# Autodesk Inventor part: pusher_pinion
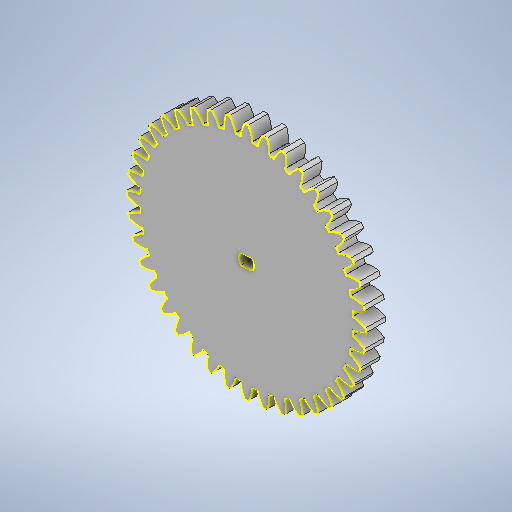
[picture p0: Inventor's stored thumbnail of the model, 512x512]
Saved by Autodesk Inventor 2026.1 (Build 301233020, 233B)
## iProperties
Company: meta-matic.com
Created: 2026-10
Part Number: pusher_pinion
Material: Generic
Description: Spur Gear - meta-matic-generator 1.3
Document SubType Name: Modeling
Designer: alolo
Authority: META-MATIC-ID: 1c046b0d7dfa
Density: 1 g/cm^3
Appearance: Default
Sending System: Open CASCADE
Preprocessor: meta-matic-generator 1.3
Title: Spur Gear_1c046b0d7dfa
Author: Takahashi Mizuki @tkhsmz
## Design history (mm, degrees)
feature "Base1"
sketch "Sketch1"
  geometry: L1 (-41.744, 1.365)-(-37.899, 1.365); L2 (-41.744, -2.135)-(-37.899, -2.135); A1 r 2.6 centre (-39.822, -0.385) between (-41.744, 1.365) and (-37.899, 1.365); 3 further points
  constraints: 4 end point, 4 point on circle, 2 midpoint, 1 centre point, 1 coincident, 1 horizontal, 1 parallel
  dimensions: "d0" = 5.2 diameter of A1; "d6" = 1.75 distance of point (-39.822, -0.385) point (-39.822, 1.365); "d7" = 1.75 distance of point (-39.822, -2.135) point (-39.822, -0.385) (= d6)
extrude "Extrusion1" cut sketch "Sketch1" stored distance "d1" = 10; taper "d2" = 0 deg
sketch "Sketch2"
  geometry: L1 (-2.379, -2.46)-(-2.292, -2.465) reference; L2 (-2.235, -0.635)-(-2.322, -0.634) reference; L3 (-2.515, 3.423)-(-2.428, 3.431) reference; L4 (-2.658, 5.248)-(-2.745, 5.235) reference; L5 (-3.57, 9.212)-(-3.485, 9.234) reference; L6 (-3.997, 10.993)-(-4.081, 10.966) reference; L7 (-5.518, 14.764)-(-5.438, 14.8) reference; L8 (-6.218, 16.457)-(-6.296, 16.418) reference; L9 (-8.31, 19.944)-(-8.236, 19.992) reference; L10 (-9.266, 21.506)-(-9.338, 21.455) reference; L11 (-11.878, 24.624)-(-11.813, 24.682) reference; L12 (-13.067, 26.017)-(-13.129, 25.955) reference; L13 (-16.134, 28.687)-(-16.079, 28.755) reference; L14 (-17.526, 29.877)-(-17.578, 29.806) reference; L15 (-20.974, 32.035)-(-20.93, 32.11) reference; L16 (-22.535, 32.992)-(-22.575, 32.914) reference; L17 (-26.277, 34.584)-(-26.246, 34.666) reference; L18 (-27.969, 35.285)-(-27.997, 35.202) reference; L19 (-31.914, 36.272)-(-31.896, 36.358) reference; L20 (-33.695, 36.7)-(-33.709, 36.614) reference; L21 (-37.746, 37.058)-(-37.741, 37.145) reference; L22 (-39.572, 37.202)-(-39.572, 37.115) reference; L23 (-43.629, 36.922)-(-43.638, 37.009) reference; L24 (-45.455, 36.779)-(-45.442, 36.692) reference; L25 (-49.418, 35.867)-(-49.44, 35.951) reference; L26 (-51.199, 35.44)-(-51.172, 35.356) reference; L27 (-54.971, 33.919)-(-55.006, 33.999) reference; L28 (-56.663, 33.219)-(-56.624, 33.141) reference; L29 (-60.151, 31.127)-(-60.198, 31.201) reference; L30 (-61.712, 30.171)-(-61.661, 30.099) reference; L31 (-64.83, 27.559)-(-64.888, 27.624) reference; L32 (-66.223, 26.37)-(-66.161, 26.308) reference; L33 (-68.893, 23.303)-(-68.961, 23.358) reference; L34 (-70.083, 21.911)-(-70.013, 21.858) reference; L35 (-72.241, 18.463)-(-72.317, 18.507) reference; L36 (-73.198, 16.902)-(-73.12, 16.862) reference; L37 (-74.79, 13.16)-(-74.872, 13.191) reference; L38 (-75.492, 11.468)-(-75.408, 11.44) reference; L39 (-76.478, 7.523)-(-76.564, 7.541) reference; L40 (-76.907, 5.742)-(-76.82, 5.728) reference; L41 (-77.264, 1.691)-(-77.352, 1.696) reference; L42 (-77.408, -0.135)-(-77.321, -0.135) reference; L43 (-77.128, -4.192)-(-77.215, -4.201) reference; L44 (-76.985, -6.018)-(-76.898, -6.005) reference; L45 (-76.073, -9.981)-(-76.158, -10.003) reference; L46 (-75.646, -11.762)-(-75.562, -11.735) reference; L47 (-74.125, -15.534)-(-74.206, -15.569) reference; L48 (-73.425, -17.226)-(-73.347, -17.187) reference; L49 (-71.333, -20.714)-(-71.407, -20.761) reference; L50 (-70.377, -22.276)-(-70.306, -22.224) reference; L51 (-67.765, -25.393)-(-67.831, -25.451) reference; L52 (-66.576, -26.786)-(-66.514, -26.724) reference; L53 (-63.509, -29.456)-(-63.564, -29.524) reference; L54 (-62.117, -30.646)-(-62.065, -30.576) reference; L55 (-58.67, -32.804)-(-58.714, -32.88) reference; L56 (-57.108, -33.761)-(-57.068, -33.683) reference; L57 (-53.366, -35.353)-(-53.398, -35.435) reference; L58 (-51.674, -36.055)-(-51.647, -35.971) reference; L59 (-47.729, -37.041)-(-47.747, -37.127) reference; L60 (-45.948, -37.47)-(-45.934, -37.383) reference; L61 (-41.897, -37.827)-(-41.902, -37.915) reference; L62 (-40.071, -37.972)-(-40.071, -37.884) reference; L63 (-36.014, -37.691)-(-36.005, -37.778) reference; L64 (-34.189, -37.548)-(-34.202, -37.461) reference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; A1 r 2.6 centre (-39.822, -0.385) between (-37.899, -2.135) and (-37.899, 1.365) reference; A2 r 37.5 centre (-39.822, -0.385) between (-2.379, -2.46) and (-2.322, -0.634) reference; A3 r 42 centre (-39.822, -0.385) between (2.16, 0.851) and (2.088, 2.37) reference; A4 r 37.5 centre (-39.822, -0.385) between (-2.515, 3.423) and (-2.745, 5.235) reference; A5 r 42 centre (-39.822, -0.385) between (1.45, 7.403) and (1.141, 8.892) reference; A6 r 37.5 centre (-39.822, -0.385) between (-3.57, 9.212) and (-4.081, 10.966) reference; A7 r 42 centre (-39.822, -0.385) between (-0.276, 13.763) and (-0.815, 15.186) reference; A8 r 37.5 centre (-39.822, -0.385) between (-5.518, 14.764) and (-6.296, 16.418) reference; A9 r 42 centre (-39.822, -0.385) between (-2.976, 19.775) and (-3.731, 21.096) reference; A10 r 37.5 centre (-39.822, -0.385) between (-8.31, 19.944) and (-9.338, 21.455) reference; A11 r 42 centre (-39.822, -0.385) between (-6.584, 25.291) and (-7.535, 26.478) reference; A12 r 37.5 centre (-39.822, -0.385) between (-11.878, 24.624) and (-13.129, 25.955) reference; A13 r 42 centre (-39.822, -0.385) between (-11.009, 30.174) and (-12.135, 31.198) reference; A14 r 37.5 centre (-39.822, -0.385) between (-16.134, 28.687) and (-17.578, 29.806) reference; A15 r 42 centre (-39.822, -0.385) between (-16.145, 34.305) and (-17.416, 35.14) reference; A16 r 37.5 centre (-39.822, -0.385) between (-20.974, 32.035) and (-22.575, 32.914) reference; A17 r 42 centre (-39.822, -0.385) between (-21.863, 37.582) and (-23.25, 38.208) reference; A18 r 37.5 centre (-39.822, -0.385) between (-26.277, 34.584) and (-27.997, 35.202) reference; A19 r 42 centre (-39.822, -0.385) between (-28.023, 39.924) and (-29.491, 40.325) reference; A20 r 37.5 centre (-39.822, -0.385) between (-31.914, 36.272) and (-33.709, 36.614) reference; A21 r 42 centre (-39.822, -0.385) between (-34.474, 41.274) and (-35.986, 41.44) reference; A22 r 37.5 centre (-39.822, -0.385) between (-37.746, 37.058) and (-39.572, 37.115) reference; A23 r 42 centre (-39.822, -0.385) between (-41.057, 41.597) and (-42.576, 41.525) reference; A24 r 37.5 centre (-39.822, -0.385) between (-43.629, 36.922) and (-45.442, 36.692) reference; A25 r 42 centre (-39.822, -0.385) between (-47.609, 40.887) and (-49.099, 40.578) reference; A26 r 37.5 centre (-39.822, -0.385) between (-49.418, 35.867) and (-51.172, 35.356) reference; A27 r 42 centre (-39.822, -0.385) between (-53.97, 39.161) and (-55.392, 38.622) reference; A28 r 37.5 centre (-39.822, -0.385) between (-54.971, 33.919) and (-56.624, 33.141) reference; A29 r 42 centre (-39.822, -0.385) between (-59.982, 36.461) and (-61.303, 35.706) reference; A30 r 37.5 centre (-39.822, -0.385) between (-60.151, 31.127) and (-61.661, 30.099) reference; A31 r 42 centre (-39.822, -0.385) between (-65.497, 32.853) and (-66.684, 31.902) reference; A32 r 37.5 centre (-39.822, -0.385) between (-64.83, 27.559) and (-66.161, 26.308) reference; A33 r 42 centre (-39.822, -0.385) between (-70.381, 28.428) and (-71.404, 27.302) reference; A34 r 37.5 centre (-39.822, -0.385) between (-68.893, 23.303) and (-70.013, 21.858) reference; A35 r 42 centre (-39.822, -0.385) between (-74.512, 23.292) and (-75.346, 22.02) reference; A36 r 37.5 centre (-39.822, -0.385) between (-72.241, 18.463) and (-73.12, 16.862) reference; A37 r 42 centre (-39.822, -0.385) between (-77.788, 17.574) and (-78.414, 16.187) reference; A38 r 37.5 centre (-39.822, -0.385) between (-74.79, 13.16) and (-75.408, 11.44) reference; A39 r 42 centre (-39.822, -0.385) between (-80.13, 11.414) and (-80.531, 9.946) reference; A40 r 37.5 centre (-39.822, -0.385) between (-76.478, 7.523) and (-76.82, 5.728) reference; A41 r 42 centre (-39.822, -0.385) between (-81.48, 4.963) and (-81.646, 3.451) reference; A42 r 37.5 centre (-39.822, -0.385) between (-77.264, 1.691) and (-77.321, -0.135) reference; A43 r 42 centre (-39.822, -0.385) between (-81.803, -1.62) and (-81.731, -3.139) reference; A44 r 37.5 centre (-39.822, -0.385) between (-77.128, -4.192) and (-76.898, -6.005) reference; A45 r 42 centre (-39.822, -0.385) between (-81.093, -8.172) and (-80.784, -9.662) reference; A46 r 37.5 centre (-39.822, -0.385) between (-76.073, -9.981) and (-75.562, -11.735) reference; A47 r 42 centre (-39.822, -0.385) between (-79.367, -14.533) and (-78.829, -15.955) reference; A48 r 37.5 centre (-39.822, -0.385) between (-74.125, -15.534) and (-73.347, -17.187) reference; A49 r 42 centre (-39.822, -0.385) between (-76.667, -20.545) and (-75.913, -21.866) reference; A50 r 37.5 centre (-39.822, -0.385) between (-71.333, -20.714) and (-70.306, -22.224) reference; A51 r 42 centre (-39.822, -0.385) between (-73.06, -26.06) and (-72.108, -27.247) reference; A52 r 37.5 centre (-39.822, -0.385) between (-67.765, -25.393) and (-66.514, -26.724) reference; A53 r 42 centre (-39.822, -0.385) between (-68.634, -30.944) and (-67.508, -31.967) reference; A54 r 37.5 centre (-39.822, -0.385) between (-63.509, -29.456) and (-62.065, -30.576) reference; A55 r 42 centre (-39.822, -0.385) between (-63.499, -35.075) and (-62.227, -35.909) reference; A56 r 37.5 centre (-39.822, -0.385) between (-58.67, -32.804) and (-57.068, -33.683) reference; A57 r 42 centre (-39.822, -0.385) between (-57.78, -38.352) and (-56.394, -38.977) reference; A58 r 37.5 centre (-39.822, -0.385) between (-53.366, -35.353) and (-51.647, -35.971) reference; A59 r 42 centre (-39.822, -0.385) between (-51.62, -40.693) and (-50.152, -41.094) reference; A60 r 37.5 centre (-39.822, -0.385) between (-47.729, -37.041) and (-45.934, -37.383) reference; A61 r 42 centre (-39.822, -0.385) between (-45.169, -42.043) and (-43.657, -42.209) reference; A62 r 37.5 centre (-39.822, -0.385) between (-41.897, -37.827) and (-40.071, -37.884) reference; A63 r 42 centre (-39.822, -0.385) between (-38.586, -42.366) and (-37.067, -42.294) reference; A64 r 37.5 centre (-39.822, -0.385) between (-36.014, -37.691) and (-34.202, -37.461) reference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; 1 further point
  constraints: 80 other
extrude "Extrusion2" cut sketch "Sketch2" distance "d3" = 3; taper "d4" = 0 deg
sketch "Sketch3"
  geometry: L1 (-41.744, -2.135)-(-37.899, -2.135) reference; L2 (-37.899, 1.365)-(-41.744, 1.365) reference; L3 (-2.515, 3.423)-(-2.428, 3.431) reference; L4 (-2.658, 5.248)-(-2.745, 5.235) reference; L5 (-3.57, 9.212)-(-3.485, 9.234) reference; L6 (-3.997, 10.993)-(-4.081, 10.966) reference; L7 (-5.518, 14.764)-(-5.438, 14.8) reference; L8 (-6.218, 16.457)-(-6.296, 16.418) reference; L9 (-8.31, 19.944)-(-8.236, 19.992) reference; L10 (-9.266, 21.506)-(-9.338, 21.455) reference; L11 (-11.878, 24.624)-(-11.813, 24.682) reference; L12 (-13.067, 26.017)-(-13.129, 25.955) reference; L13 (-16.134, 28.687)-(-16.079, 28.755) reference; L14 (-17.526, 29.877)-(-17.578, 29.806) reference; L15 (-20.974, 32.035)-(-20.93, 32.11) reference; L16 (-22.535, 32.992)-(-22.575, 32.914) reference; L17 (-26.277, 34.584)-(-26.246, 34.666) reference; L18 (-27.969, 35.285)-(-27.997, 35.202) reference; L19 (-31.914, 36.272)-(-31.896, 36.358) reference; L20 (-33.695, 36.7)-(-33.709, 36.614) reference; L21 (-37.746, 37.058)-(-37.741, 37.145) reference; L22 (-39.572, 37.202)-(-39.572, 37.115) reference; L23 (-43.629, 36.922)-(-43.638, 37.009) reference; L24 (-45.455, 36.779)-(-45.442, 36.692) reference; L25 (-49.418, 35.867)-(-49.44, 35.951) reference; L26 (-51.199, 35.44)-(-51.172, 35.356) reference; L27 (-54.971, 33.919)-(-55.006, 33.999) reference; L28 (-56.663, 33.219)-(-56.624, 33.141) reference; L29 (-60.151, 31.127)-(-60.198, 31.201) reference; L30 (-61.712, 30.171)-(-61.661, 30.099) reference; L31 (-64.83, 27.559)-(-64.888, 27.624) reference; L32 (-66.223, 26.37)-(-66.161, 26.308) reference; L33 (-68.893, 23.303)-(-68.961, 23.358) reference; L34 (-70.083, 21.911)-(-70.013, 21.858) reference; L35 (-72.241, 18.463)-(-72.317, 18.507) reference; L36 (-73.198, 16.902)-(-73.12, 16.862) reference; L37 (-74.79, 13.16)-(-74.872, 13.191) reference; L38 (-75.492, 11.468)-(-75.408, 11.44) reference; L39 (-76.478, 7.523)-(-76.564, 7.541) reference; L40 (-76.907, 5.742)-(-76.82, 5.728) reference; L41 (-77.264, 1.691)-(-77.352, 1.696) reference; L42 (-77.408, -0.135)-(-77.321, -0.135) reference; L43 (-77.128, -4.192)-(-77.215, -4.201) reference; L44 (-76.985, -6.018)-(-76.898, -6.005) reference; L45 (-76.073, -9.981)-(-76.158, -10.003) reference; L46 (-75.646, -11.762)-(-75.562, -11.735) reference; L47 (-74.125, -15.534)-(-74.206, -15.569) reference; L48 (-73.425, -17.226)-(-73.347, -17.187) reference; L49 (-71.333, -20.714)-(-71.407, -20.761) reference; L50 (-70.377, -22.276)-(-70.306, -22.224) reference; L51 (-67.765, -25.393)-(-67.831, -25.451) reference; L52 (-66.576, -26.786)-(-66.514, -26.724) reference; L53 (-63.509, -29.456)-(-63.564, -29.524) reference; L54 (-62.117, -30.646)-(-62.065, -30.576) reference; L55 (-58.67, -32.804)-(-58.714, -32.88) reference; L56 (-57.108, -33.761)-(-57.068, -33.683) reference; L57 (-53.366, -35.353)-(-53.398, -35.435) reference; L58 (-51.674, -36.055)-(-51.647, -35.971) reference; L59 (-47.729, -37.041)-(-47.747, -37.127) reference; L60 (-45.948, -37.47)-(-45.934, -37.383) reference; L61 (-41.897, -37.827)-(-41.902, -37.915) reference; L62 (-40.071, -37.972)-(-40.071, -37.884) reference; L63 (-36.014, -37.691)-(-36.005, -37.778) reference; L64 (-34.189, -37.548)-(-34.202, -37.461) reference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; A1 r 2.6 centre (-39.822, -0.385) between (-41.744, 1.365) and (-41.744, -2.135) reference; A2 r 2.6 centre (-39.822, -0.385) between (-37.899, -2.135) and (-37.899, 1.365) reference; A3 r 37.5 centre (-39.822, -0.385) between (-2.515, 3.423) and (-2.745, 5.235) reference; A4 r 42 centre (-39.822, -0.385) between (1.45, 7.403) and (1.141, 8.892) reference; A5 r 37.5 centre (-39.822, -0.385) between (-3.57, 9.212) and (-4.081, 10.966) reference; A6 r 42 centre (-39.822, -0.385) between (-0.276, 13.763) and (-0.815, 15.186) reference; A7 r 37.5 centre (-39.822, -0.385) between (-5.518, 14.764) and (-6.296, 16.418) reference; A8 r 42 centre (-39.822, -0.385) between (-2.976, 19.775) and (-3.731, 21.096) reference; A9 r 37.5 centre (-39.822, -0.385) between (-8.31, 19.944) and (-9.338, 21.455) reference; A10 r 42 centre (-39.822, -0.385) between (-6.584, 25.291) and (-7.535, 26.478) reference; A11 r 37.5 centre (-39.822, -0.385) between (-11.878, 24.624) and (-13.129, 25.955) reference; A12 r 42 centre (-39.822, -0.385) between (-11.009, 30.174) and (-12.135, 31.198) reference; A13 r 37.5 centre (-39.822, -0.385) between (-16.134, 28.687) and (-17.578, 29.806) reference; A14 r 42 centre (-39.822, -0.385) between (-16.145, 34.305) and (-17.416, 35.14) reference; A15 r 37.5 centre (-39.822, -0.385) between (-20.974, 32.035) and (-22.575, 32.914) reference; A16 r 42 centre (-39.822, -0.385) between (-21.863, 37.582) and (-23.25, 38.208) reference; A17 r 37.5 centre (-39.822, -0.385) between (-26.277, 34.584) and (-27.997, 35.202) reference; A18 r 42 centre (-39.822, -0.385) between (-28.023, 39.924) and (-29.491, 40.325) reference; A19 r 37.5 centre (-39.822, -0.385) between (-31.914, 36.272) and (-33.709, 36.614) reference; A20 r 42 centre (-39.822, -0.385) between (-34.474, 41.274) and (-35.986, 41.44) reference; A21 r 37.5 centre (-39.822, -0.385) between (-37.746, 37.058) and (-39.572, 37.115) reference; A22 r 42 centre (-39.822, -0.385) between (-41.057, 41.597) and (-42.576, 41.525) reference; A23 r 37.5 centre (-39.822, -0.385) between (-43.629, 36.922) and (-45.442, 36.692) reference; A24 r 42 centre (-39.822, -0.385) between (-47.609, 40.887) and (-49.099, 40.578) reference; A25 r 37.5 centre (-39.822, -0.385) between (-49.418, 35.867) and (-51.172, 35.356) reference; A26 r 42 centre (-39.822, -0.385) between (-53.97, 39.161) and (-55.392, 38.622) reference; A27 r 37.5 centre (-39.822, -0.385) between (-54.971, 33.919) and (-56.624, 33.141) reference; A28 r 42 centre (-39.822, -0.385) between (-59.982, 36.461) and (-61.303, 35.706) reference; A29 r 37.5 centre (-39.822, -0.385) between (-60.151, 31.127) and (-61.661, 30.099) reference; A30 r 42 centre (-39.822, -0.385) between (-65.497, 32.853) and (-66.684, 31.902) reference; A31 r 37.5 centre (-39.822, -0.385) between (-64.83, 27.559) and (-66.161, 26.308) reference; A32 r 42 centre (-39.822, -0.385) between (-70.381, 28.428) and (-71.404, 27.302) reference; A33 r 37.5 centre (-39.822, -0.385) between (-68.893, 23.303) and (-70.013, 21.858) reference; A34 r 42 centre (-39.822, -0.385) between (-74.512, 23.292) and (-75.346, 22.02) reference; A35 r 37.5 centre (-39.822, -0.385) between (-72.241, 18.463) and (-73.12, 16.862) reference; A36 r 42 centre (-39.822, -0.385) between (-77.788, 17.574) and (-78.414, 16.187) reference; A37 r 37.5 centre (-39.822, -0.385) between (-74.79, 13.16) and (-75.408, 11.44) reference; A38 r 42 centre (-39.822, -0.385) between (-80.13, 11.414) and (-80.531, 9.946) reference; A39 r 37.5 centre (-39.822, -0.385) between (-76.478, 7.523) and (-76.82, 5.728) reference; A40 r 42 centre (-39.822, -0.385) between (-81.48, 4.963) and (-81.646, 3.451) reference; A41 r 37.5 centre (-39.822, -0.385) between (-77.264, 1.691) and (-77.321, -0.135) reference; A42 r 42 centre (-39.822, -0.385) between (-81.803, -1.62) and (-81.731, -3.139) reference; A43 r 37.5 centre (-39.822, -0.385) between (-77.128, -4.192) and (-76.898, -6.005) reference; A44 r 42 centre (-39.822, -0.385) between (-81.093, -8.172) and (-80.784, -9.662) reference; A45 r 37.5 centre (-39.822, -0.385) between (-76.073, -9.981) and (-75.562, -11.735) reference; A46 r 42 centre (-39.822, -0.385) between (-79.367, -14.533) and (-78.829, -15.955) reference; A47 r 37.5 centre (-39.822, -0.385) between (-74.125, -15.534) and (-73.347, -17.187) reference; A48 r 42 centre (-39.822, -0.385) between (-76.667, -20.545) and (-75.913, -21.866) reference; A49 r 37.5 centre (-39.822, -0.385) between (-71.333, -20.714) and (-70.306, -22.224) reference; A50 r 42 centre (-39.822, -0.385) between (-73.06, -26.06) and (-72.108, -27.247) reference; A51 r 37.5 centre (-39.822, -0.385) between (-67.765, -25.393) and (-66.514, -26.724) reference; A52 r 42 centre (-39.822, -0.385) between (-68.634, -30.944) and (-67.508, -31.967) reference; A53 r 37.5 centre (-39.822, -0.385) between (-63.509, -29.456) and (-62.065, -30.576) reference; A54 r 42 centre (-39.822, -0.385) between (-63.499, -35.075) and (-62.227, -35.909) reference; A55 r 37.5 centre (-39.822, -0.385) between (-58.67, -32.804) and (-57.068, -33.683) reference; A56 r 42 centre (-39.822, -0.385) between (-57.78, -38.352) and (-56.394, -38.977) reference; A57 r 37.5 centre (-39.822, -0.385) between (-53.366, -35.353) and (-51.647, -35.971) reference; A58 r 42 centre (-39.822, -0.385) between (-51.62, -40.693) and (-50.152, -41.094) reference; A59 r 37.5 centre (-39.822, -0.385) between (-47.729, -37.041) and (-45.934, -37.383) reference; A60 r 42 centre (-39.822, -0.385) between (-45.169, -42.043) and (-43.657, -42.209) reference; A61 r 37.5 centre (-39.822, -0.385) between (-41.897, -37.827) and (-40.071, -37.884) reference; A62 r 42 centre (-39.822, -0.385) between (-38.586, -42.366) and (-37.067, -42.294) reference; A63 r 37.5 centre (-39.822, -0.385) between (-36.014, -37.691) and (-34.202, -37.461) reference; A64 r 42 centre (-39.822, -0.385) between (-32.034, -41.656) and (-30.545, -41.347) reference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; 1 further point
  constraints: 80 other
  node "Projected Loop2"
body "Solid1"
node "Projected Loop1"
